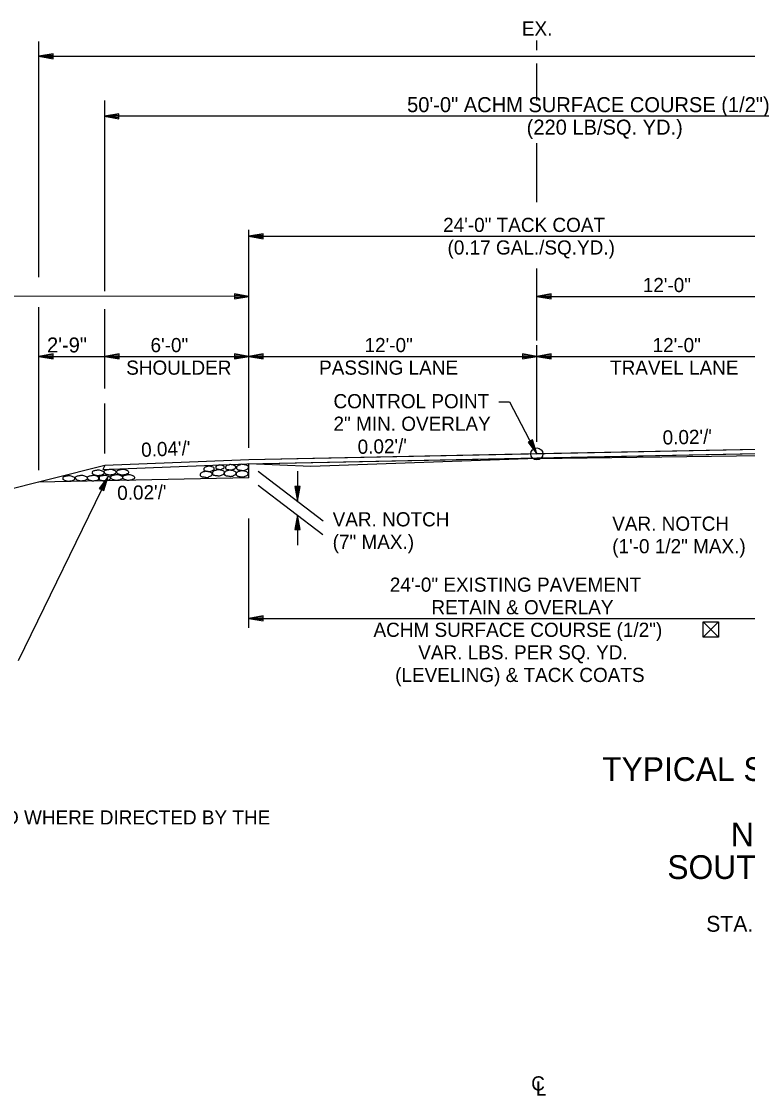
# Model space of a CAD drawing. Extents: x 1398183 to 1398373, y 1967240 to 1968889.
# Drawn here: x 1398220.37 to 1398250.61, y 1967604.21 to 1967648.95 of the extents above; entities that cross this region are included whole.
import ezdxf

# ---------------------------------------------------------------- set-up
doc = ezdxf.new("R2010")
doc.units = 0
for name, color, linetype in [('1', 7, 'Continuous'), ('10', 7, 'Continuous'), ('19', 7, 'Continuous'), ('42', 7, 'Continuous'), ('7', 7, 'Continuous'), ('Level 1', 7, 'Continuous'), ('Level 9', 7, 'Continuous')]:
    doc.layers.add(name, color=color, linetype=linetype)

# ---------------------------------------------------------------- blocks, each defined once
blk = doc.blocks.new('ROCKS')
at = {"layer": '1'}
blk.add_spline([(0.013, 0.06), (0.053, 0.053), (0.107, 0.033), (0.133, 0.013), (0.133, -0.007), (0.12, -0.033), (0.107, -0.04), (0.073, -0.053), (0.033, -0.067), (0.013, -0.067), (-0.02, -0.06), (-0.06, -0.053), (-0.087, -0.047), (-0.113, -0.02), (-0.113, -0.007), (-0.107, 0.02), (-0.087, 0.033), (-0.067, 0.047), (-0.033, 0.053), (-0.02, 0.06), (0.013, 0.06)], degree=3, dxfattribs=at)

msp = doc.modelspace()

# ---------------------------------------------------------------- linework, layer by layer
at = {"layer": '10'}
for p, q in [((1398249.404, 1967623.944), (1398248.763, 1967623.303)), ((1398248.763, 1967623.944), (1398249.404, 1967623.303)), ((1398249.023, 1967623.303), (1398249.011, 1967623.303))]:
    msp.add_line(p, q, dxfattribs=at)
msp.add_lwpolyline([(1398249.011, 1967623.303), (1398248.763, 1967623.303), (1398248.763, 1967623.944), (1398249.404, 1967623.944), (1398249.404, 1967623.303), (1398249.023, 1967623.303)], dxfattribs=at)
at = {"layer": '19'}
for p, q in [((1398221.092, 1967638.301), (1398221.092, 1967648.126)), ((1398221.692, 1967647.609), (1398221.092, 1967647.504)), ((1398221.092, 1967647.504), (1398278.376, 1967647.504)), ((1398221.092, 1967647.504), (1398221.692, 1967647.399)), ((1398221.692, 1967647.554), (1398221.252, 1967647.519)), ((1398221.252, 1967647.489), (1398221.692, 1967647.449)), ((1398221.692, 1967647.399), (1398221.692, 1967647.609)), ((1398223.838, 1967637.714), (1398223.838, 1967645.662)), ((1398224.431, 1967645.109), (1398223.831, 1967645.005)), ((1398273.831, 1967645.004), (1398223.831, 1967645.005)), ((1398223.831, 1967645.005), (1398224.431, 1967644.899)), ((1398224.431, 1967645.054), (1398223.991, 1967645.019)), ((1398223.991, 1967644.989), (1398224.431, 1967644.949)), ((1398224.431, 1967644.899), (1398224.431, 1967645.109)), ((1398229.838, 1967631.197), (1398229.838, 1967640.269)), ((1398230.438, 1967640.109), (1398229.838, 1967640.005)), ((1398229.838, 1967640.005), (1398283.763, 1967640.004)), ((1398229.838, 1967640.005), (1398230.438, 1967639.899)), ((1398230.438, 1967640.054), (1398229.998, 1967640.02)), ((1398229.998, 1967639.99), (1398230.438, 1967639.949)), ((1398230.438, 1967639.899), (1398230.438, 1967640.109)), ((1398229.238, 1967637.61), (1398229.238, 1967637.4)), ((1398229.838, 1967637.504), (1398229.238, 1967637.61)), ((1398229.678, 1967637.52), (1398229.238, 1967637.555)), ((1398242.438, 1967637.609), (1398241.838, 1967637.504)), ((1398242.438, 1967637.554), (1398241.998, 1967637.519)), ((1398242.438, 1967637.399), (1398242.438, 1967637.609)), ((1398229.838, 1967637.504), (1398205.838, 1967637.505)), ((1398229.238, 1967637.4), (1398229.838, 1967637.504)), ((1398229.238, 1967637.45), (1398229.678, 1967637.49)), ((1398241.838, 1967637.504), (1398253.838, 1967637.504)), ((1398241.838, 1967637.504), (1398242.438, 1967637.399)), ((1398241.998, 1967637.489), (1398242.438, 1967637.449)), ((1398221.092, 1967630.27), (1398221.092, 1967637.049)), ((1398223.838, 1967633.66), (1398223.838, 1967636.974)), ((1398241.838, 1967631.437), (1398241.838, 1967635.474)), ((1398221.692, 1967635.109), (1398221.092, 1967635.004)), ((1398221.092, 1967635.004), (1398229.838, 1967635.004)), ((1398221.092, 1967635.004), (1398221.692, 1967634.899)), ((1398221.692, 1967635.054), (1398221.252, 1967635.019)), ((1398221.252, 1967634.989), (1398221.692, 1967634.949)), ((1398221.692, 1967634.899), (1398221.692, 1967635.109)), ((1398224.438, 1967635.109), (1398223.838, 1967635.004)), ((1398223.838, 1967635.004), (1398224.438, 1967634.899)), ((1398224.438, 1967635.054), (1398223.998, 1967635.019)), ((1398223.998, 1967634.989), (1398224.438, 1967634.949)), ((1398224.438, 1967634.899), (1398224.438, 1967635.109)), ((1398229.238, 1967635.109), (1398229.238, 1967634.899)), ((1398229.838, 1967635.004), (1398229.238, 1967635.109)), ((1398229.678, 1967635.019), (1398229.238, 1967635.054)), ((1398229.238, 1967634.899), (1398229.838, 1967635.004)), ((1398229.238, 1967634.949), (1398229.678, 1967634.989)), ((1398230.438, 1967635.109), (1398229.838, 1967635.004)), ((1398229.838, 1967635.004), (1398230.438, 1967634.899)), ((1398229.838, 1967635.004), (1398241.838, 1967635.004)), ((1398230.438, 1967635.054), (1398229.998, 1967635.019)), ((1398229.998, 1967634.989), (1398230.438, 1967634.949)), ((1398230.438, 1967634.899), (1398230.438, 1967635.109)), ((1398241.238, 1967635.11), (1398241.238, 1967634.9)), ((1398241.838, 1967635.004), (1398241.238, 1967635.11)), ((1398241.678, 1967635.02), (1398241.238, 1967635.055)), ((1398241.238, 1967634.9), (1398241.838, 1967635.004)), ((1398241.238, 1967634.95), (1398241.678, 1967634.99)), ((1398242.438, 1967635.109), (1398241.838, 1967635.004)), ((1398241.838, 1967635.004), (1398253.838, 1967635.004)), ((1398241.838, 1967635.004), (1398242.438, 1967634.899)), ((1398242.438, 1967635.054), (1398241.998, 1967635.019)), ((1398241.998, 1967634.989), (1398242.438, 1967634.949)), ((1398242.438, 1967634.899), (1398242.438, 1967635.109)), ((1398223.838, 1967630.957), (1398223.838, 1967633.043)), ((1398241.66, 1967631.52), (1398241.474, 1967631.425)), ((1398241.474, 1967631.425), (1398241.838, 1967630.937)), ((1398241.517, 1967631.443), (1398241.752, 1967631.074)), ((1398241.776, 1967631.083), (1398241.615, 1967631.491)), ((1398241.838, 1967630.937), (1398241.66, 1967631.52)), ((1398223.838, 1967630.457), (1398205.838, 1967625.957)), ((1398223.838, 1967630.457), (1398223.753, 1967630.287)), ((1398229.838, 1967630.697), (1398223.838, 1967630.457)), ((1398229.838, 1967629.945), (1398229.838, 1967630.529)), ((1398220.246, 1967622.336), (1398223.974, 1967629.994)), ((1398223.974, 1967629.994), (1398223.61, 1967629.506)), ((1398223.797, 1967629.413), (1398223.974, 1967629.994)), ((1398230.235, 1967630.226), (1398232.937, 1967628.158)), ((1398231.867, 1967630.227), (1398231.867, 1967628.977)), ((1398223.61, 1967629.506), (1398223.797, 1967629.413)), ((1398223.891, 1967629.858), (1398223.659, 1967629.484)), ((1398223.753, 1967629.436), (1398223.917, 1967629.845)), ((1398230.235, 1967629.642), (1398232.917, 1967627.589)), ((1398231.972, 1967629.577), (1398231.762, 1967629.577)), ((1398231.762, 1967629.577), (1398231.867, 1967628.977)), ((1398231.817, 1967629.577), (1398231.852, 1967629.137)), ((1398231.867, 1967628.977), (1398231.972, 1967629.577)), ((1398231.882, 1967629.137), (1398231.922, 1967629.577)), ((1398229.838, 1967623.701), (1398229.838, 1967628.256)), ((1398231.867, 1967628.392), (1398231.762, 1967627.792)), ((1398231.852, 1967628.232), (1398231.817, 1967627.792)), ((1398231.972, 1967627.792), (1398231.867, 1967628.392)), ((1398231.867, 1967628.392), (1398231.867, 1967627.142)), ((1398231.922, 1967627.792), (1398231.882, 1967628.232)), ((1398231.762, 1967627.792), (1398231.972, 1967627.792)), ((1398230.438, 1967624.196), (1398229.838, 1967624.091)), ((1398230.438, 1967624.141), (1398229.998, 1967624.106)), ((1398230.438, 1967623.986), (1398230.438, 1967624.196)), ((1398229.838, 1967624.091), (1398230.438, 1967623.986)), ((1398229.838, 1967624.091), (1398253.838, 1967624.091)), ((1398229.998, 1967624.076), (1398230.438, 1967624.036))]:
    msp.add_line(p, q, dxfattribs=at)
for points in [[(1398240.258, 1967633.113), (1398240.704, 1967633.113), (1398241.837, 1967630.936)], [(1398223.753, 1967630.287), (1398229.753, 1967630.527), (1398241.838, 1967630.77), (1398253.838, 1967631.01), (1398265.922, 1967630.767), (1398273.923, 1967630.447)], [(1398253.838, 1967631.177), (1398241.838, 1967630.937), (1398229.838, 1967630.697)], [(1398229.838, 1967629.945), (1398221.092, 1967629.77)]]:
    msp.add_lwpolyline(points, dxfattribs=at)
msp.add_lwpolyline([(1398223.753, 1967630.287), (1398229.753, 1967630.527), (1398253.838, 1967631.01), (1398265.922, 1967630.767), (1398273.923, 1967630.447), (1398273.838, 1967630.617), (1398265.837, 1967630.937), (1398253.838, 1967631.177), (1398229.838, 1967630.697), (1398223.838, 1967630.457)], close=True, dxfattribs=at)
at = {"layer": '42'}
for points in [[(1398241.847, 1967630.754), (1398251.195, 1967630.869), (1398253.837, 1967631.011)], [(1398241.847, 1967630.754), (1398232.424, 1967630.417), (1398229.838, 1967630.53)]]:
    msp.add_lwpolyline(points, dxfattribs=at)
at = {"layer": '7'}
for p, q in [((1398241.835, 1967647.765), (1398241.835, 1967648.156)), ((1398241.835, 1967645.662), (1398241.835, 1967647.198)), ((1398241.838, 1967641.433), (1398241.837, 1967643.882)), ((1398241.838, 1967635.659), (1398241.838, 1967638.659))]:
    msp.add_line(p, q, dxfattribs=at)
at = {"layer": 'Level 9'}
msp.add_circle((1398241.838, 1967630.937), 0.25, dxfattribs=at)

# ---------------------------------------------------------------- block references
at = {"layer": '1', "xscale": 1.9687338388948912, "yscale": -1.9687338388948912}
for p in [(1398222.322, 1967629.913), (1398222.847, 1967629.926), (1398223.346, 1967629.926), (1398223.543, 1967630.149), (1398223.805, 1967629.926), (1398224.041, 1967630.176), (1398224.317, 1967629.953), (1398224.566, 1967630.176), (1398224.816, 1967629.953)]:
    msp.add_blockref('ROCKS', p, dxfattribs=at)
at = {"layer": 'Level 1'}
for p, xscale, yscale, rotation in [((1398228.165, 1967630.321), 1.7594110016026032, 1.7594110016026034, 1.8263814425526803), ((1398228.622, 1967630.389), 1.4397665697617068, 1.439766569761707, 1.8263814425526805), ((1398229.063, 1967630.387), 1.742879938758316, 1.742879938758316, 1.8263814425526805), ((1398229.557, 1967630.381), 2.011654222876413, 2.011654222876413, 1.8263814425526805), ((1398228.043, 1967630.095), 2.011654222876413, 2.011654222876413, 1.8263814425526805), ((1398228.551, 1967630.158), 2.011654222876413, 2.011654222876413, 1.8263814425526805), ((1398229.045, 1967630.139), 2.011654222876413, 2.011654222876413, 1.8263814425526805), ((1398229.542, 1967630.114), 2.011654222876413, 2.011654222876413, 1.8263814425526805)]:
    msp.add_blockref('ROCKS', p, dxfattribs=dict(at, xscale=xscale, yscale=yscale, rotation=rotation))

# ---------------------------------------------------------------- texts
at = {"layer": '10'}
for s, height, p in [('6\'-0"', 0.59, (1398225.744, 1967635.179)), ('12\'-0"', 0.59, (1398234.66, 1967635.179)), ('12\'-0"', 0.59, (1398246.66, 1967635.179)), ('SHOULDER', 0.59, (1398224.731, 1967634.239)), ('PASSING LANE', 0.59001, (1398232.767, 1967634.239)), ('TRAVEL LANE', 0.59001, (1398244.888, 1967634.239)), ('CONTROL POINT', 0.59001, (1398233.367, 1967632.842)), ('2" MIN. OVERLAY', 0.59001, (1398233.367, 1967631.902)), ('VAR. NOTCH', 0.59, (1398233.331, 1967627.922)), ('VAR. NOTCH', 0.59, (1398244.978, 1967627.741)), ('(7" MAX.)', 0.59, (1398233.331, 1967626.982)), ('(1\'-0 1/2" MAX.)', 0.59001, (1398244.978, 1967626.801))]:
    msp.add_text(s, height=height, dxfattribs=at).set_placement(p)
for s, height, rotation, p in [("0.04'/'", 0.59, 2.2906, (1398225.364, 1967630.813)), ('24\'-0" EXISTING PAVEMENT', 0.59001, 0, (1398235.714, 1967625.199)), ('RETAIN & OVERLAY', 0.59001, 0, (1398237.445, 1967624.259)), ('ACHM SURFACE COURSE (1/2")', 0.59001, 0, (1398235.033, 1967623.319)), ('VAR. LBS. PER SQ. YD.', 0.59001, 0, (1398236.896, 1967622.379)), ('(LEVELING) & TACK COATS', 0.59001, 0, (1398235.935, 1967621.439)), ('TO BE USED IF AND WHERE DIRECTED BY THE ', 0.59001, 360, (1398212.672, 1967615.504))]:
    msp.add_text(s, height=height, rotation=rotation, dxfattribs=at).set_placement(p)
at = {"layer": '19'}
for s, rotation, p in [('EX.', 0, (1398241.213, 1967648.363)), ('12\'-0"', 0, (1398246.249, 1967637.68)), ("0.02'/'", 1.1458, (1398247.083, 1967631.329)), ("0.02'/'", 1.1458, (1398234.378, 1967630.941)), ("0.02'/'", 1.1458, (1398224.362, 1967629.02))]:
    msp.add_text(s, height=0.59, rotation=rotation, dxfattribs=at).set_placement(p)
for s, height, p in [('50\'-0" ACHM SURFACE COURSE (1/2")', 0.625, (1398236.433, 1967645.176)), ('(220 LB/SQ. YD.)', 0.625, (1398241.414, 1967644.239)), ('2\'-9"', 0.625, (1398221.433, 1967635.166)), ('TYPICAL SECTION OF IMPROVEMENT', 0.98999, (1398244.558, 1967617.317)), ('NOTCH AND WIDENING', 0.98999, (1398249.921, 1967614.595)), ('SOUTHBOUND PASSING LANE', 0.98999, (1398247.274, 1967613.234)), ('STA. 472+02.80 TO STA. 491+39.79', 0.65999, (1398248.893, 1967611.036)), ('C', 0.59, (1398241.603, 1967604.425)), ('L', 0.59, (1398241.797, 1967604.214))]:
    msp.add_text(s, height=height, dxfattribs=at).set_placement(p)
at = {"layer": '42'}
for s, p in [('24\'-0" TACK COAT', (1398237.934, 1967640.185)), ('(0.17 GAL./SQ.YD.)', (1398238.117, 1967639.245))]:
    msp.add_text(s, height=0.59001, rotation=360, dxfattribs=at).set_placement(p)

doc.saveas('drawing.dxf')
